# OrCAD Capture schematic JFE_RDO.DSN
size A; title: JFE150 COMPRESSOR; rev: 1.0
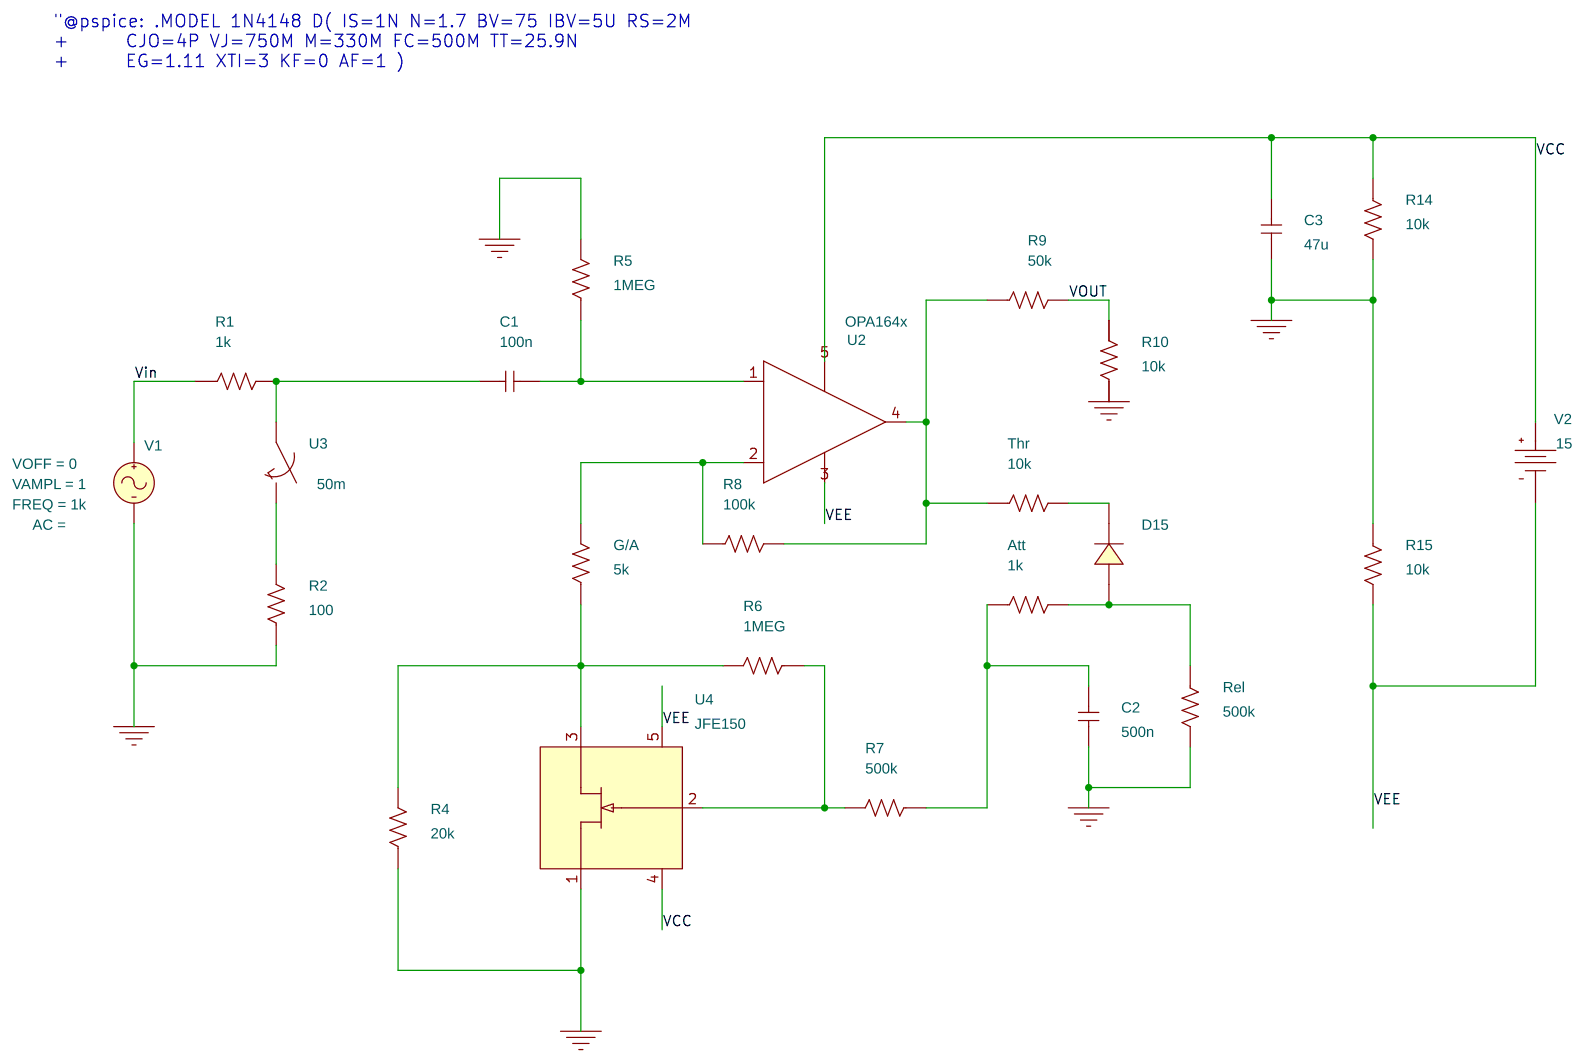
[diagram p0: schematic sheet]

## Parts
Att  1k  [AXRC05]
C1  100n  [cap196]
C2  500n  [cap196]
C3  47u  [cap196]
D15  1N4148
G/A  5k  [AXRC05]
R1  1k  [AXRC05]
R2  100  [AXRC05]
R4  20k  [AXRC05]
R5  1MEG  [AXRC05]
R6  1MEG  [AXRC05]
R7  500k  [AXRC05]
R8  100k  [AXRC05]
R9  50k  [AXRC05]
R10  10k  [AXRC05]
R14  10k  [AXRC05]
R15  10k  [AXRC05]
Rel  500k  [AXRC05]
Thr  10k  [AXRC05]
U2  OPA164x
U3  Switch Closes at T
U4  JFE150
V1  VSIN
V2  VDC

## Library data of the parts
Att G/A R1 R2 R4-R10 R14 R15 Rel Thr = R
C1-C3 = C
D15 = D_D1
U2 = OPA164x: Testbenches: [{"testbenchurl":"https://software-dl.ti.com/pspice/esd/models/OPA164x_V2.0.zip","testbenchopj":"OPA164x_Test_Circuit.OPJ","testbenchdisplayname":"OPA164x PSpice Model"}]; productURL: http://www.ti.com/document-viewer/OPA1641/datasheet/
U3 = Sw_tClose: ROPEN: 1G; TCLOSE: 50m; TTRAN: 200n
U4 = JFE150
V1 = VSIN: FREQ: 1k; VAMPL: 1; VOFF: 0
V2 = VDC: DC: 15

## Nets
VCC: C3.2 R14.1 U2.5(V+) U4.4(VCC) V2.0(+)
VEE: R15.2 U2.3(V-) U4.5(VEE) V2.1(-)
Vin: R1.1 V1.1(+)
0: C2.1 C3.1 R2.1 R4.1 R5.2 R10.1 R14.2 R15.1 Rel.2 U4.1(D) V1.2(-)
VOUT: R9.2 R10.2
N00585: C1.1 R1.2 U3.1
N00590: C1.2 R5.1 U2.1(+)
N00659: G/A.1 R4.2 R6.2 U4.3(S)
N00818: G/A.2 R8.1 U2.2(-)
N00888: R8.2 R9.1 Thr.1 U2.4(OUT)
N00980: D15.1(C) Thr.2
N01130: Att.1 C2.2 R7.1
N01137: R6.1 R7.2 U4.2(G)
N01159: Att.2 D15.2(A) Rel.1
N03665: R2.2 U3.2

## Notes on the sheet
- "@pspice: .MODEL 1N4148 D( IS=1N N=1.7 BV=75 IBV=5U RS=2M
  +      CJO=4P VJ=750M M=330M FC=500M TT=25.9N
  +      EG=1.11 XTI=3 KF=0 AF=1 )
